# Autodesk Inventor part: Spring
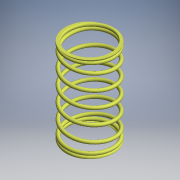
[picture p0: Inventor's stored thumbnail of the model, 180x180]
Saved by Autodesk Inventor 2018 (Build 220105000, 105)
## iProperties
Shininess: 24.0
Compacted: True
Length Units: 11272
Angle Units: 11279
Time Units: 11290
Mass Units: 11286
Length Display Precision: 4
Angle Display Precision: 2
Company: Autodesk
Created: 2000-03
Part Number: Spring
Project: Inventor Samples
User Status: IN PROGRESS
Document SubType Name: Modeling
Designer: Autodesk, Inc.
Density: 8.03 g/cm^3
Material: Stainless Steel, Austenitic
Mass: 2.926 g
Surface Area: 14.1446 cm^2
Volume: 0.364384 cm^3
Appearance: Black
Density: 0.0
Volumn: 0.0
Area: 0.0
PropertySet Name: Model Information
Control State: 0
Master: False
Checked Out: False
Author: Autodesk, Inc.
Revision Number: A
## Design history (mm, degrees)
sketch "Sketch2"
  geometry: L1 (-14.979, -10.854)-(-14.979, 14.546); A1 r 0.546 centre (-22.51, -11.4) between (-21.964, -11.4) and (-22.51, -10.854); 1 further point
  constraints: 2 end point, 2 horizontal alignment, 2 point on circle, 2 vertical alignment, 1 centre point, 1 vertical, 5 other
  dimensions: "d0" = 25.4 distance of L1.start L1.end; "d1" = 13.97 diameter of A1.start L1; "d2" = 1.0922 diameter of A1
node "Coil1" dims "d3" = 3.175 (= 0.125 x d0), "d4" = 25.4, "d5" = 50, "d6" = 0, "d7" = 30 deg, "d8" = 1 deg, "d9" = 30 deg, "d10" = 1 deg
workaxis "Work Axis1"
node "Coil2" dims "d11" = 1.1176 (computed from d2), "d12" = 25.4, "d13" = 20, "d14" = 0, "d15" = 90 deg, "d16" = 90 deg, "d17" = 0, "d18" = 0
  sketch "Sketch3"
    geometry: L1 (7.531, -5.981)-(7.531, 31.384) reference; C1 r 0.546 at (0, 0) reference
node "Extrusion1" dims "d19" = 25.4, "d20" = 0
  sketch "Sketch4"
    geometry: L1 (-2.213, -5.605)-(17.486, -5.605); L2 (17.486, -5.605)-(17.486, 0.546); L3 (17.486, 0.546)-(-2.213, 0.546); L4 (-2.213, 0.546)-(-2.213, -5.605); C1 r 0.546 at (0, 0) reference
    constraints: 8 end point, 2 parallel, 1 horizontal, 1 perpendicular, 1 tangent
node "Coil3" dims "d21" = 1.1176 (computed from d2), "d22" = 25.4, "d23" = 20, "d24" = 0, "d25" = 90 deg, "d26" = 90 deg, "d27" = 0, "d28" = 0
  sketch "Sketch5"
    geometry: L1 (-7.531, -31.381)-(-7.531, 5.984) reference; C1 r 0.546 at (0, 0) reference
node "Extrusion2" dims "d29" = 25.4, "d30" = 0
  sketch "Sketch6"
    geometry: L1 (7.067, 10.583)-(-19.265, 10.583); L2 (-19.265, 10.583)-(-19.265, -0.546); L3 (-19.265, -0.546)-(7.067, -0.546); L4 (7.067, -0.546)-(7.067, 10.583); C1 r 0.546 at (0, 0) reference
    constraints: 8 end point, 2 parallel, 1 horizontal, 1 perpendicular, 1 tangent
body "Solid1"
